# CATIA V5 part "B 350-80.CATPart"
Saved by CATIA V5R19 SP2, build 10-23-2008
Part number: B 350-80
Bounding box of the stored display mesh (mm): x -15.868 to 15.868, y -15.868 to 15.868, z 0 to 210
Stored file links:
  C:\Users\Bora\Desktop\3D Katı model\B serisi\B 350\B 350-80.CATPart
  C:\Program Files\Dassault Systemes\B19\intel_a\reffiles\standard\MetricThickPitch.txt
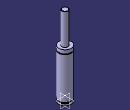
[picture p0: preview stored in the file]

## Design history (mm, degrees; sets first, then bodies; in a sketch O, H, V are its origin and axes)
Body1 (main body)
  Sketch1 on yz-plane, origin (0, 0, 0), H (0, 1, 0), V (0, 0, 1)
    point P1 (16, 118.5)
    point P4 (16, 116.5)
    point P7 (16, 118.5)
    point P8 (16, 116.5)
    point P9 (8, 209)
    point P11 (8, 209)
    line L1 (16, 118.5) -> (16, 128)
    line L2 (16, 7.5) -> (16, 116.5)
    line L3 (13.5, 7.5) -> (13.5, 4)
    arc A1 centre (16, 117.5) radius 1 from (16, 118.5) to (16, 116.5) ccw
    arc A2 centre (7, 209) radius 1 from (8, 209) to (7, 210) ccw
    line L4 (8, 209) -> (8, 128)
    line L5 (16, 0) -> (16, 4)
    line L6 (7, 210) -> (0, 210)
    point P15 (0, 210)
    line L7 (8, 128) -> (16, 128)
    line L8 (0, 0) -> (16, 0)
    line L9 (13.5, 7.5) -> (16, 7.5)
    line L10 (13.5, 4) -> (16, 4)
    coincidence: P15 V, P1 P7, P4 P8, P9 P11
    tangency: L6 A2
    horizontal: L7 H, L8 H, L9 H, L10 H
  Shaft1: profile Sketch1, axis Sketch1.V, angle 360
  Sketch2 on face of Shaft1 from Sketch1.L8, origin (0, 0, 0), H (1, 0, 0), V (0, -1, 0)
    point P1 (0, 0)
  Hole1: placed by Sketch2, at (0, 0, 0) direction (0, 0, 1), diameter 6.647, depth 7, threaded "M8", thread diameter 8, thread depth 7, pitch 1.25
